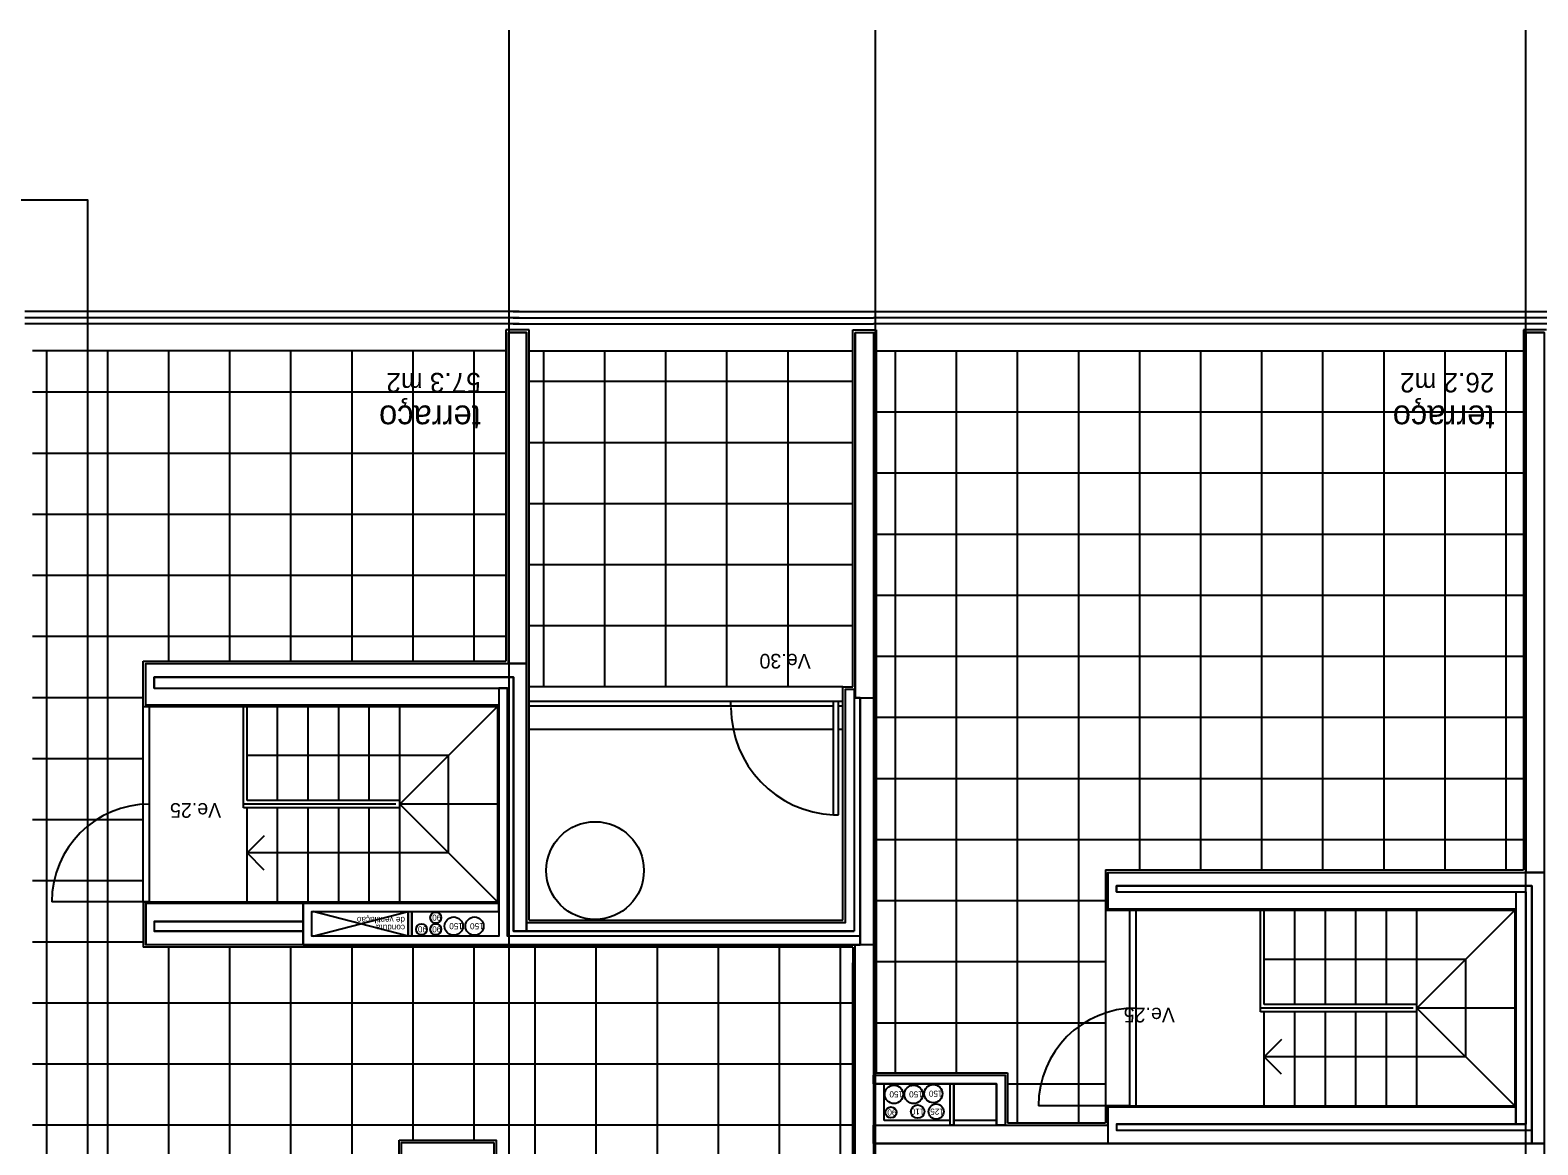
# Model space of a CAD drawing. Extents: x 1278 to 1356, y -253.7 to -224.
# Drawn here: x 1311.64 to 1323.98, y -238.74 to -229.62 of the extents above; entities that cross this region are included whole.
import ezdxf

# ---------------------------------------------------------------- set-up
doc = ezdxf.new("R2010")
doc.units = 0
for name, color, linetype in [('corte', 7, 'Continuous'), ('estereoctomias', 7, 'Continuous'), ('estrutura-eixos', 7, 'Continuous'), ('Level 1', 7, 'Continuous'), ('Level 13', 7, 'Continuous'), ('Level 2', 7, 'Continuous'), ('Level 21', 7, 'Continuous'), ('Level 3', 7, 'Continuous'), ('Level 40', 7, 'Continuous'), ('Level 41', 7, 'Continuous'), ('Level 59', 7, 'Continuous'), ('Level 60', 7, 'Continuous'), ('portas', 7, 'Continuous'), ('revestimentos', 7, 'Continuous'), ('vista', 7, 'Continuous')]:
    doc.layers.add(name, color=color, linetype=linetype)

msp = doc.modelspace()

# ---------------------------------------------------------------- linework, layer by layer
at = {"layer": 'corte'}
for p, q in [((1318.394, -232.094), (1318.544, -232.094)), ((1318.394, -232.094), (1318.394, -235.084)), ((1324.034, -232.094), (1323.884, -232.094)), ((1312.584, -235.145), (1312.584, -234.805)), ((1312.654, -235.005), (1312.654, -234.915)), ((1315.595, -234.915), (1315.595, -236.994)), ((1315.545, -235.005), (1315.545, -237.036)), ((1318.313, -236.924), (1318.313, -235.014)), ((1318.313, -235.014), (1318.394, -235.014)), ((1318.384, -235.014), (1318.384, -236.994)), ((1318.394, -235.084), (1318.544, -235.084)), ((1318.434, -235.084), (1318.434, -237.106)), ((1320.533, -236.624), (1323.933, -236.624)), ((1320.533, -236.674), (1320.533, -236.624)), ((1323.933, -236.624), (1323.933, -238.624)), ((1312.584, -236.765), (1312.584, -237.106)), ((1313.873, -237.106), (1313.873, -236.765)), ((1320.533, -236.674), (1323.884, -236.674)), ((1323.884, -236.674), (1323.884, -238.574)), ((1313.873, -236.996), (1312.654, -236.996)), ((1315.559, -237.106), (1312.584, -237.106)), ((1318.544, -238.174), (1319.621, -238.174)), ((1318.544, -238.244), (1319.551, -238.244)), ((1319.171, -238.584), (1319.171, -238.244)), ((1319.201, -238.584), (1319.201, -238.244)), ((1319.551, -238.244), (1319.551, -238.584)), ((1319.621, -238.174), (1319.621, -238.584))]:
    msp.add_line(p, q, dxfattribs=at)
for points in [[(1314.733, -237.036), (1313.943, -237.036), (1313.943, -236.835), (1314.733, -236.835)], [(1315.474, -237.036), (1314.763, -237.036), (1314.763, -236.835), (1315.474, -236.835)], [(1315.433, -238.726), (1315.433, -239.066), (1314.679, -239.066), (1314.679, -238.726)]]:
    msp.add_lwpolyline(points, close=True, dxfattribs=at)
at = {"layer": 'estereoctomias'}
for points in [[(1315.703, -234.805), (1315.553, -234.805), (1315.553, -232.094), (1315.703, -232.094)], [(1318.394, -232.094), (1318.544, -232.094), (1318.544, -243.754), (1318.394, -243.754), (1318.394, -237.106), (1318.434, -237.106), (1318.434, -235.084), (1318.394, -235.084)], [(1324.034, -236.514), (1323.884, -236.514), (1323.884, -232.094), (1324.034, -232.094)], [(1315.474, -235.145), (1312.584, -235.145), (1312.584, -234.805), (1315.703, -234.805), (1315.703, -234.915), (1315.703, -236.994), (1315.595, -236.994), (1315.595, -234.915), (1312.654, -234.915), (1312.654, -235.005), (1315.474, -235.005)], [(1318.434, -237.036), (1315.545, -237.036), (1315.545, -235.005), (1315.474, -235.005), (1315.474, -237.036), (1313.943, -237.036), (1313.943, -236.835), (1315.474, -236.835), (1315.474, -236.765), (1313.873, -236.765), (1313.873, -237.106), (1318.434, -237.106)], [(1318.384, -236.994), (1315.703, -236.994), (1315.703, -236.924), (1318.313, -236.924), (1318.313, -235.014), (1318.384, -235.014), (1318.384, -236.924)], [(1324.034, -236.514), (1324.034, -236.624), (1324.034, -238.734), (1323.933, -238.734), (1323.933, -236.624), (1320.533, -236.624), (1320.533, -236.674), (1323.884, -236.674), (1323.884, -236.814), (1323.884, -238.574), (1323.803, -238.574), (1323.803, -236.814), (1320.463, -236.814), (1320.463, -236.514)], [(1313.873, -237.106), (1312.584, -237.106), (1312.584, -236.765), (1313.873, -236.765), (1313.873, -236.915), (1312.654, -236.915), (1312.654, -236.996), (1313.873, -236.996)], [(1314.763, -237.036), (1314.733, -237.036), (1314.733, -236.835), (1314.763, -236.835)], [(1319.621, -238.584), (1319.551, -238.584), (1319.551, -238.244), (1318.544, -238.244), (1318.544, -238.174), (1319.621, -238.174)], [(1319.201, -238.584), (1319.171, -238.584), (1319.171, -238.244), (1319.201, -238.244)], [(1323.933, -238.624), (1323.933, -238.734), (1323.803, -238.734), (1318.544, -238.734), (1318.544, -238.584), (1320.463, -238.584), (1320.463, -238.434), (1323.803, -238.434), (1323.803, -238.574), (1320.533, -238.574), (1320.533, -238.624), (1323.803, -238.624)], [(1324.034, -240.114), (1323.884, -240.114), (1323.884, -238.734), (1324.034, -238.734)]]:
    msp.add_lwpolyline(points, close=True, dxfattribs=at)
at = {"layer": 'estrutura-eixos'}
for p, q in [((1315.559, -250.792), (1315.559, -229.62)), ((1318.559, -250.792), (1318.559, -229.62)), ((1323.884, -250.792), (1323.884, -229.62))]:
    msp.add_line(p, q, dxfattribs=at)
at = {"layer": 'Level 1'}
for p, q in [((1315.703, -232.094), (1315.553, -232.094)), ((1315.553, -232.094), (1315.553, -234.805)), ((1315.703, -236.994), (1315.703, -232.094)), ((1318.544, -232.094), (1318.544, -243.754)), ((1323.884, -232.094), (1323.884, -236.514)), ((1312.584, -234.805), (1315.703, -234.805)), ((1312.654, -234.915), (1315.595, -234.915)), ((1312.654, -235.005), (1315.545, -235.005)), ((1315.474, -235.005), (1315.474, -236.765)), ((1312.584, -235.145), (1315.474, -235.145)), ((1320.463, -236.514), (1324.034, -236.514)), ((1320.463, -236.514), (1320.463, -236.814)), ((1312.584, -236.765), (1315.474, -236.765)), ((1323.803, -236.674), (1323.803, -238.574)), ((1320.463, -236.814), (1323.803, -236.814)), ((1312.654, -236.915), (1312.654, -236.996)), ((1312.654, -236.915), (1313.873, -236.915)), ((1315.595, -236.994), (1318.384, -236.994)), ((1315.703, -236.924), (1318.313, -236.924)), ((1318.434, -237.036), (1315.545, -237.036)), ((1318.544, -237.106), (1315.559, -237.106)), ((1318.394, -243.754), (1318.394, -237.106)), ((1320.463, -238.434), (1323.803, -238.434)), ((1320.463, -238.434), (1320.463, -238.734)), ((1318.544, -238.584), (1320.463, -238.584)), ((1320.533, -238.574), (1323.884, -238.574)), ((1320.533, -238.574), (1320.533, -238.624)), ((1320.533, -238.624), (1323.933, -238.624)), ((1318.544, -238.734), (1324.034, -238.734)), ((1323.884, -240.114), (1323.884, -238.734))]:
    msp.add_line(p, q, dxfattribs=at)
at = {"layer": 'Level 13'}
for p, q in [((1312.564, -236.755), (1312.564, -235.155)), ((1312.614, -236.755), (1312.614, -235.155)), ((1312.614, -236.755), (1311.814, -236.755)), ((1320.643, -238.424), (1320.643, -236.824)), ((1320.693, -238.424), (1320.693, -236.824))]:
    msp.add_line(p, q, dxfattribs=at)
for centre in [(1312.614, -236.755), (1320.693, -238.424)]:
    msp.add_arc(centre, 0.8, 90, 180, dxfattribs=at)
at = {"layer": 'Level 2'}
for p, q in [((1315.493, -231.924), (1311.593, -231.924)), ((1315.643, -231.924), (1315.493, -231.924)), ((1315.593, -231.924), (1318.543, -231.924)), ((1318.543, -231.924), (1345.543, -231.924)), ((1315.643, -231.974), (1311.593, -231.974)), ((1315.643, -232.024), (1311.593, -232.024)), ((1315.593, -231.974), (1318.543, -231.974)), ((1315.593, -232.024), (1318.543, -232.024)), ((1345.543, -231.974), (1318.543, -231.974)), ((1345.543, -232.024), (1318.543, -232.024)), ((1315.533, -232.244), (1311.658, -232.244)), ((1315.723, -232.244), (1318.374, -232.244)), ((1318.564, -232.244), (1323.864, -232.244)), ((1318.293, -234.994), (1315.723, -234.994)), ((1313.384, -235.985), (1313.384, -235.155)), ((1313.414, -235.925), (1313.414, -235.155)), ((1313.414, -235.925), (1313.414, -235.155)), ((1313.664, -235.925), (1313.664, -235.155)), ((1313.914, -235.925), (1313.914, -235.155)), ((1314.164, -235.925), (1314.164, -235.155)), ((1314.414, -235.925), (1314.414, -235.155)), ((1314.664, -235.925), (1314.664, -235.155)), ((1314.664, -235.955), (1315.464, -235.155)), ((1318.293, -235.114), (1315.723, -235.114)), ((1318.216, -235.154), (1315.723, -235.154)), ((1317.375, -235.154), (1317.375, -235.114)), ((1318.216, -236.044), (1318.216, -235.114)), ((1318.256, -235.114), (1318.216, -235.114)), ((1318.256, -236.044), (1318.256, -235.114)), ((1318.293, -235.154), (1318.256, -235.154)), ((1318.216, -235.344), (1315.723, -235.344)), ((1318.293, -235.344), (1318.256, -235.344)), ((1313.414, -235.555), (1315.064, -235.555)), ((1315.064, -236.355), (1315.064, -235.555)), ((1314.633, -235.955), (1313.384, -235.955)), ((1314.664, -235.985), (1313.384, -235.985)), ((1314.664, -235.925), (1313.414, -235.925)), ((1313.414, -236.755), (1313.414, -235.985)), ((1313.664, -236.755), (1313.664, -235.985)), ((1313.914, -236.755), (1313.914, -235.985)), ((1314.164, -236.755), (1314.164, -235.985)), ((1314.414, -236.755), (1314.414, -235.985)), ((1314.664, -235.985), (1314.664, -235.925)), ((1315.464, -235.955), (1314.664, -235.955)), ((1314.664, -235.955), (1315.464, -236.755)), ((1314.664, -236.755), (1314.664, -235.985)), ((1318.216, -236.044), (1318.256, -236.044)), ((1313.555, -236.214), (1313.414, -236.355)), ((1315.064, -236.355), (1313.414, -236.355)), ((1313.555, -236.497), (1313.414, -236.355)), ((1320.443, -236.824), (1320.443, -238.424)), ((1321.713, -237.654), (1321.713, -236.824)), ((1321.743, -237.594), (1321.743, -236.824)), ((1321.743, -237.594), (1321.743, -236.824)), ((1321.993, -237.594), (1321.993, -236.824)), ((1322.243, -237.594), (1322.243, -236.824)), ((1322.493, -237.594), (1322.493, -236.824)), ((1322.743, -237.594), (1322.743, -236.824)), ((1322.993, -237.594), (1322.993, -236.824)), ((1322.993, -237.624), (1323.793, -236.824)), ((1321.743, -237.224), (1323.393, -237.224)), ((1323.393, -238.024), (1323.393, -237.224)), ((1322.962, -237.624), (1321.713, -237.624)), ((1322.993, -237.594), (1321.743, -237.594)), ((1322.993, -237.654), (1322.993, -237.594)), ((1323.793, -237.624), (1322.993, -237.624)), ((1322.993, -237.624), (1323.793, -238.424)), ((1322.993, -237.654), (1321.713, -237.654)), ((1321.743, -238.424), (1321.743, -237.654)), ((1321.993, -238.424), (1321.993, -237.654)), ((1322.243, -238.424), (1322.243, -237.654)), ((1322.493, -238.424), (1322.493, -237.654)), ((1322.743, -238.424), (1322.743, -237.654)), ((1322.993, -238.424), (1322.993, -237.654)), ((1321.885, -237.883), (1321.743, -238.024)), ((1323.393, -238.024), (1321.743, -238.024)), ((1321.885, -238.165), (1321.743, -238.024))]:
    msp.add_line(p, q, dxfattribs=at)
msp.add_circle((1316.263, -236.499), 0.4, dxfattribs=at)
at = {"layer": 'Level 21'}
for p, q in [((1311.773, -243.604), (1311.773, -232.244)), ((1312.273, -243.604), (1312.273, -232.244)), ((1312.773, -234.785), (1312.773, -232.244)), ((1313.273, -234.785), (1313.273, -232.244)), ((1313.773, -234.785), (1313.773, -232.244)), ((1314.273, -234.785), (1314.273, -232.244)), ((1314.773, -234.785), (1314.773, -232.244)), ((1315.273, -234.785), (1315.273, -232.244)), ((1315.843, -234.994), (1315.843, -232.249)), ((1316.343, -234.994), (1316.343, -232.249)), ((1316.843, -234.994), (1316.843, -232.249)), ((1317.343, -234.994), (1317.343, -232.249)), ((1317.843, -234.994), (1317.843, -232.249)), ((1318.723, -238.154), (1318.723, -232.244)), ((1319.223, -238.154), (1319.223, -232.244)), ((1319.723, -238.564), (1319.723, -232.244)), ((1320.223, -238.564), (1320.223, -232.244)), ((1320.723, -236.494), (1320.723, -232.244)), ((1321.223, -236.494), (1321.223, -232.244)), ((1321.723, -236.494), (1321.723, -232.244)), ((1322.223, -236.494), (1322.223, -232.244)), ((1322.723, -236.494), (1322.723, -232.244)), ((1323.223, -236.494), (1323.223, -232.244)), ((1323.723, -236.494), (1323.723, -232.244)), ((1315.723, -232.494), (1318.374, -232.494)), ((1315.533, -232.584), (1311.658, -232.584)), ((1318.564, -232.744), (1323.864, -232.744)), ((1315.723, -232.994), (1318.374, -232.994)), ((1315.533, -233.084), (1311.658, -233.084)), ((1318.564, -233.244), (1323.864, -233.244)), ((1315.723, -233.494), (1318.374, -233.494)), ((1315.533, -233.584), (1311.658, -233.584)), ((1318.564, -233.744), (1323.864, -233.744)), ((1315.723, -233.994), (1318.374, -233.994)), ((1315.533, -234.084), (1311.658, -234.084)), ((1318.564, -234.244), (1323.864, -234.244)), ((1315.723, -234.494), (1318.374, -234.494)), ((1315.533, -234.584), (1311.658, -234.584)), ((1318.564, -234.744), (1323.864, -234.744)), ((1312.564, -235.084), (1311.658, -235.084)), ((1318.564, -235.244), (1323.864, -235.244)), ((1312.564, -235.584), (1311.658, -235.584)), ((1318.564, -235.744), (1323.864, -235.744)), ((1312.564, -236.084), (1311.658, -236.084)), ((1318.564, -236.244), (1323.864, -236.244)), ((1312.564, -236.584), (1311.658, -236.584)), ((1318.564, -236.744), (1320.443, -236.744)), ((1312.564, -237.084), (1311.658, -237.084)), ((1312.773, -243.604), (1312.773, -237.126)), ((1313.273, -243.604), (1313.273, -237.126)), ((1313.773, -243.604), (1313.773, -237.126)), ((1314.273, -243.604), (1314.273, -237.126)), ((1314.773, -238.706), (1314.773, -237.126)), ((1315.273, -238.706), (1315.273, -237.126)), ((1315.773, -243.604), (1315.773, -237.126)), ((1316.273, -243.604), (1316.273, -237.126)), ((1316.773, -243.604), (1316.773, -237.126)), ((1317.273, -243.604), (1317.273, -237.126)), ((1317.773, -243.604), (1317.773, -237.126)), ((1318.273, -243.604), (1318.273, -237.126)), ((1318.564, -237.244), (1320.443, -237.244)), ((1318.374, -237.584), (1311.658, -237.584)), ((1318.564, -237.744), (1320.443, -237.744)), ((1318.374, -238.084), (1311.658, -238.084)), ((1319.641, -238.244), (1320.443, -238.244)), ((1318.374, -238.584), (1311.658, -238.584))]:
    msp.add_line(p, q, dxfattribs=at)
at = {"layer": 'Level 3'}
msp.add_arc((1318.256, -235.164), 0.88, 180, 267.3962, dxfattribs=at)
at = {"layer": 'Level 41'}
for p, q in [((1314.733, -237.036), (1313.953, -236.835)), ((1313.953, -237.036), (1314.733, -236.835))]:
    msp.add_line(p, q, dxfattribs=at)
for centre, radius in [((1314.959, -236.884), 0.045), ((1315.106, -236.954), 0.075), ((1315.276, -236.954), 0.075), ((1314.842, -236.98), 0.045), ((1314.959, -236.98), 0.045), ((1318.71, -238.331), 0.075), ((1318.871, -238.331), 0.075), ((1319.033, -238.325), 0.075), ((1318.686, -238.479), 0.045), ((1318.905, -238.472), 0.055), ((1319.056, -238.472), 0.0625)]:
    msp.add_circle(centre, radius, dxfattribs=at)
at = {"layer": 'Level 59'}
msp.add_lwpolyline([(1312.108, -244.886), (1306.965, -244.886), (1306.965, -231.008), (1312.108, -231.008)], close=True, dxfattribs=at)
at = {"layer": 'portas'}
msp.add_line((1320.643, -238.424), (1319.893, -238.424), dxfattribs=at)
at = {"layer": 'revestimentos'}
for p, q in [((1315.723, -232.074), (1315.533, -232.074)), ((1315.533, -232.074), (1315.533, -234.785)), ((1315.723, -236.904), (1315.723, -232.074)), ((1318.374, -232.074), (1318.564, -232.074)), ((1318.374, -234.994), (1318.374, -232.074)), ((1318.564, -232.074), (1318.564, -238.154)), ((1323.864, -232.074), (1323.864, -236.494)), ((1324.054, -232.074), (1323.864, -232.074)), ((1312.564, -234.785), (1315.533, -234.785)), ((1312.564, -235.155), (1312.564, -234.785)), ((1318.293, -236.904), (1318.293, -234.994)), ((1318.293, -234.994), (1318.374, -234.994)), ((1312.564, -235.155), (1315.464, -235.155)), ((1315.464, -235.155), (1315.464, -236.755)), ((1320.443, -236.494), (1320.443, -236.824)), ((1320.443, -236.494), (1323.864, -236.494)), ((1312.564, -236.755), (1315.464, -236.755)), ((1312.564, -236.755), (1312.564, -237.126)), ((1320.443, -236.824), (1323.793, -236.824)), ((1323.793, -236.824), (1323.793, -238.424)), ((1315.723, -236.904), (1318.293, -236.904)), ((1315.559, -237.126), (1312.564, -237.126)), ((1318.374, -237.126), (1315.559, -237.126)), ((1318.374, -237.126), (1318.374, -243.774)), ((1318.374, -243.774), (1318.374, -237.254)), ((1318.564, -238.154), (1319.641, -238.154)), ((1319.641, -238.154), (1319.641, -238.564)), ((1320.443, -238.424), (1320.443, -238.564)), ((1320.443, -238.424), (1323.793, -238.424)), ((1319.641, -238.564), (1320.443, -238.564))]:
    msp.add_line(p, q, dxfattribs=at)
msp.add_lwpolyline([(1314.659, -238.706), (1315.453, -238.706), (1315.453, -239.086), (1314.659, -239.086)], close=True, dxfattribs=at)
at = {"layer": 'vista'}
for p, q in [((1318.631, -238.544), (1318.631, -238.244)), ((1319.171, -238.544), (1318.631, -238.544)), ((1319.551, -238.544), (1319.201, -238.544))]:
    msp.add_line(p, q, dxfattribs=at)

# ---------------------------------------------------------------- texts
at = {"layer": 'corte'}
for s, p in [('de ventilação ', (1314.707, -236.878)), ('conduta', (1314.707, -236.942))]:
    msp.add_text(s, height=0.05, rotation=180, dxfattribs=at).set_placement(p)
at = {"layer": 'Level 40'}
for s, p in [('Ve.30', (1318.029, -234.725)), ('Ve.25', (1313.202, -235.947)), ('Ve.25', (1321.011, -237.622))]:
    msp.add_text(s, height=0.12, rotation=180, dxfattribs=at).set_placement(p)
at = {"layer": 'Level 41'}
for s, p in [('90', (1315.004, -236.859)), ('90', (1314.887, -236.955)), ('90', (1315.004, -236.955)), ('150', (1315.181, -236.929)), ('150', (1315.351, -236.929)), ('150', (1318.785, -238.306)), ('150', (1318.946, -238.306)), ('150', (1319.108, -238.3)), ('90', (1318.731, -238.454)), ('110', (1318.96, -238.447)), ('125', (1319.119, -238.447))]:
    msp.add_text(s, height=0.05, rotation=180, dxfattribs=at).set_placement(p)
at = {"layer": 'Level 60'}
for s, height, p in [('57.3 m2', 0.16, (1315.327, -232.425)), ('26.2 m2', 0.16, (1323.627, -232.425)), ('terraço', 0.2, (1315.327, -232.692)), ('terraço', 0.2, (1323.627, -232.692))]:
    msp.add_text(s, height=height, rotation=180, dxfattribs=at).set_placement(p)

doc.saveas('drawing.dxf')
